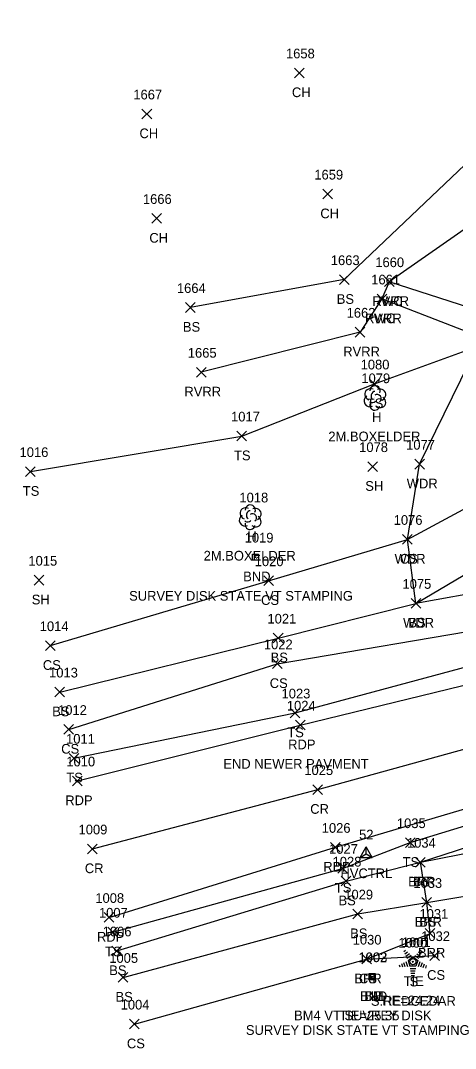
# Model space of a CAD drawing. Extents: x 1443064 to 1445163, y 544063 to 544655.
# Drawn here: x 1443063.6 to 1443153.5, y 544062.5 to 544274.6 of the extents above; entities that cross this region are included whole.
import ezdxf

# ---------------------------------------------------------------- set-up
doc = ezdxf.new("R2010")
doc.units = 0
for name, color, linetype in [('C_A', 7, 'Continuous'), ('C_C', 7, 'Continuous'), ('C_I', 7, 'Continuous'), ('CBP', 7, 'Continuous'), ('CPBM', 7, 'Continuous'), ('CPSM', 7, 'Continuous'), ('L_A', 7, 'Continuous'), ('L_C', 7, 'Continuous'), ('L_I', 7, 'Continuous'), ('L_TIC', 7, 'Continuous'), ('LABL', 7, 'Continuous'), ('LAWA', 7, 'Continuous'), ('LAWE', 7, 'Continuous'), ('LELB', 7, 'Continuous'), ('LTC', 7, 'Continuous'), ('LTD', 7, 'Continuous'), ('M_A', 7, 'Continuous'), ('M_C', 7, 'Continuous'), ('M_I', 7, 'Continuous'), ('MHBP', 7, 'Continuous'), ('P_A', 7, 'Continuous'), ('P_C', 7, 'Continuous'), ('P_I', 7, 'Continuous'), ('P_TIC', 7, 'Continuous'), ('PET', 7, 'Continuous'), ('PRC', 7, 'Continuous')]:
    doc.layers.add(name, color=color, linetype=linetype)

msp = doc.modelspace()

# ---------------------------------------------------------------- linework, layer by layer
at = {"layer": 'CBP'}
for centre, radius in [((1443144.67, 544080.41), 0.625), ((1443144.67, 544080.41), 0.0833), ((1443136.24, 544077.31), 0.625), ((1443136.24, 544077.31), 0.0833)]:
    msp.add_circle(centre, radius, dxfattribs=at)
at = {"layer": 'CPBM'}
for p, q in [((1443135.8, 544076.82), (1443135.8, 544077.82)), ((1443135.8, 544077.82), (1443136.8, 544077.82)), ((1443136.8, 544076.82), (1443135.8, 544076.82)), ((1443136.3, 544077.32), (1443136.3, 544077.32)), ((1443136.3, 544077.32), (1443136.3, 544077.32)), ((1443136.8, 544077.82), (1443136.8, 544076.82))]:
    msp.add_line(p, q, dxfattribs=at)
at = {"layer": 'CPSM'}
for p, q in [((1443133.76, 544101.93), (1443135.01, 544104.09)), ((1443136.26, 544101.93), (1443135.01, 544104.09)), ((1443135.02, 544102.65), (1443135.01, 544104.09)), ((1443133.76, 544101.93), (1443135.02, 544102.65)), ((1443133.76, 544101.93), (1443136.26, 544101.93)), ((1443135.02, 544102.65), (1443135.02, 544102.65)), ((1443135.02, 544102.65), (1443136.26, 544101.93))]:
    msp.add_line(p, q, dxfattribs=at)
at = {"layer": 'L_TIC'}
for points in [[(1443120.19, 544262.82), (1443122.19, 544264.82)], [(1443122.19, 544262.82), (1443120.19, 544264.82)], [(1443088.72, 544254.35), (1443090.72, 544256.35)], [(1443090.72, 544254.35), (1443088.72, 544256.35)], [(1443126.06, 544237.82), (1443128.06, 544239.82)], [(1443128.06, 544237.82), (1443126.06, 544239.82)], [(1443090.76, 544232.79), (1443092.76, 544234.79)], [(1443092.76, 544232.79), (1443090.76, 544234.79)], [(1443129.5, 544220.16), (1443131.5, 544222.16)], [(1443131.5, 544220.16), (1443129.5, 544222.16)], [(1443138.78, 544219.74), (1443140.78, 544221.74)], [(1443140.78, 544219.74), (1443138.78, 544221.74)], [(1443138.78, 544219.74), (1443140.78, 544221.74)], [(1443140.78, 544219.74), (1443138.78, 544221.74)], [(1443097.72, 544214.41), (1443099.72, 544216.41)], [(1443099.72, 544214.41), (1443097.72, 544216.41)], [(1443137.28, 544216.17), (1443139.28, 544218.17)], [(1443139.28, 544216.17), (1443137.28, 544218.17)], [(1443137.28, 544216.17), (1443139.28, 544218.17)], [(1443139.28, 544216.17), (1443137.28, 544218.17)], [(1443132.77, 544209.32), (1443134.77, 544211.32)], [(1443134.77, 544209.32), (1443132.77, 544211.32)], [(1443099.97, 544201.05), (1443101.97, 544203.05)], [(1443101.97, 544201.05), (1443099.97, 544203.05)], [(1443135.73, 544198.63), (1443137.73, 544200.63)], [(1443137.73, 544198.63), (1443135.73, 544200.63)], [(1443108.31, 544187.89), (1443110.31, 544189.89)], [(1443110.31, 544187.89), (1443108.31, 544189.89)], [(1443064.69, 544180.55), (1443066.69, 544182.55)], [(1443066.69, 544180.55), (1443064.69, 544182.55)], [(1443135.34, 544181.58), (1443137.34, 544183.58)], [(1443137.34, 544181.58), (1443135.34, 544183.58)], [(1443145.04, 544182.08), (1443147.04, 544184.08)], [(1443147.04, 544182.08), (1443145.04, 544184.08)], [(1443142.53, 544166.56), (1443144.53, 544168.56)], [(1443144.53, 544166.56), (1443142.53, 544168.56)], [(1443142.53, 544166.56), (1443144.53, 544168.56)], [(1443144.53, 544166.56), (1443142.53, 544168.56)], [(1443066.46, 544158.14), (1443068.46, 544160.14)], [(1443068.46, 544158.14), (1443066.46, 544160.14)], [(1443113.86, 544158.03), (1443115.86, 544160.03)], [(1443115.86, 544158.03), (1443113.86, 544160.03)], [(1443144.28, 544153.36), (1443146.28, 544155.36)], [(1443146.28, 544153.36), (1443144.28, 544155.36)], [(1443144.28, 544153.36), (1443146.28, 544155.36)], [(1443146.28, 544153.36), (1443144.28, 544155.36)], [(1443068.8, 544144.63), (1443070.8, 544146.63)], [(1443070.8, 544144.63), (1443068.8, 544146.63)], [(1443115.84, 544146.19), (1443117.84, 544148.19)], [(1443117.84, 544146.19), (1443115.84, 544148.19)], [(1443115.66, 544140.89), (1443117.66, 544142.89)], [(1443117.66, 544140.89), (1443115.66, 544142.89)], [(1443070.73, 544135.06), (1443072.73, 544137.06)], [(1443072.73, 544135.06), (1443070.73, 544137.06)], [(1443119.32, 544130.74), (1443121.32, 544132.74)], [(1443121.32, 544130.74), (1443119.32, 544132.74)], [(1443072.59, 544127.34), (1443074.59, 544129.34)], [(1443074.59, 544127.34), (1443072.59, 544129.34)], [(1443073.67, 544121.4), (1443075.67, 544123.4)], [(1443075.67, 544121.4), (1443073.67, 544123.4)], [(1443143.13, 544103.98), (1443145.13, 544105.98)], [(1443145.13, 544103.98), (1443143.13, 544105.98)], [(1443145.21, 544099.93), (1443147.21, 544101.93)], [(1443147.21, 544099.93), (1443145.21, 544101.93)], [(1443145.21, 544099.93), (1443147.21, 544101.93)], [(1443147.21, 544099.93), (1443145.21, 544101.93)], [(1443129.13, 544098.67), (1443131.13, 544100.67)], [(1443131.13, 544098.67), (1443129.13, 544100.67)], [(1443129.86, 544096.05), (1443131.86, 544098.05)], [(1443131.86, 544096.05), (1443129.86, 544098.05)], [(1443146.52, 544091.64), (1443148.52, 544093.64)], [(1443148.52, 544091.64), (1443146.52, 544093.64)], [(1443146.52, 544091.64), (1443148.52, 544093.64)], [(1443148.52, 544091.64), (1443146.52, 544093.64)], [(1443132.27, 544089.26), (1443134.27, 544091.26)], [(1443134.27, 544089.26), (1443132.27, 544091.26)], [(1443081.68, 544085.51), (1443083.68, 544087.51)], [(1443083.68, 544085.51), (1443081.68, 544087.51)], [(1443147.23, 544085.26), (1443149.23, 544087.26)], [(1443149.23, 544085.26), (1443147.23, 544087.26)], [(1443082.51, 544081.64), (1443084.51, 544083.64)], [(1443084.51, 544081.64), (1443082.51, 544083.64)], [(1443148.15, 544080.67), (1443150.15, 544082.67)], [(1443150.15, 544080.67), (1443148.15, 544082.67)], [(1443134.09, 544079.94), (1443136.09, 544081.94)], [(1443136.09, 544079.94), (1443134.09, 544081.94)], [(1443134.09, 544079.94), (1443136.09, 544081.94)], [(1443136.09, 544079.94), (1443134.09, 544081.94)], [(1443083.81, 544076.17), (1443085.81, 544078.17)], [(1443085.81, 544076.17), (1443083.81, 544078.17)], [(1443086.16, 544066.54), (1443088.16, 544068.54)], [(1443088.16, 544066.54), (1443086.16, 544068.54)]]:
    msp.add_lwpolyline(points, dxfattribs=at)
at = {"layer": 'LABL'}
msp.add_lwpolyline([(1443135.09, 544080.94), (1443148.23, 544086.26), (1443147.52, 544092.64), (1443146.21, 544100.93), (1443174.96, 544106.59), (1443195.01, 544110.55), (1443196.95, 544107.58), (1443201, 544099.13), (1443204.98, 544089.82), (1443210.37, 544081.53)], dxfattribs=at)
at = {"layer": 'LAWA'}
msp.add_lwpolyline([(1443161.29, 544157.23), (1443145.28, 544154.36), (1443143.53, 544167.56), (1443146.04, 544183.08), (1443157.94, 544207.35), (1443163.64, 544207.35), (1443166.87, 544211.98), (1443169.79, 544215.76), (1443171.76, 544225.15), (1443198.4, 544243.33), (1443223.22, 544247.5), (1443248.61, 544240.73), (1443289.53, 544254.52), (1443328.33, 544272.01), (1443354.38, 544286)], dxfattribs=at)
at = {"layer": 'LAWE'}
for points in [[(1443627.73, 544516.96), (1443602.93, 544465.06), (1443560.09, 544445.87), (1443514.11, 544419.1), (1443476.33, 544389.4), (1443439.4, 544357.75), (1443402.97, 544339.11), (1443368.14, 544318.06), (1443323.16, 544292.42), (1443281.44, 544273.46), (1443240.37, 544261.14), (1443193.33, 544260.65), (1443164.34, 544237.83), (1443139.78, 544220.74), (1443138.28, 544217.17), (1443133.77, 544210.32), (1443100.97, 544202.05)], [(1443196.33, 544167.63), (1443194.95, 544177.18), (1443185.57, 544192.33), (1443177.49, 544199.81), (1443166.87, 544211.98), (1443139.78, 544220.74)], [(1443194.34, 544166.63), (1443188.72, 544173.88), (1443182.02, 544189.58), (1443171.16, 544195.16), (1443163.64, 544207.35), (1443138.28, 544217.17)]]:
    msp.add_lwpolyline(points, dxfattribs=at)
at = {"layer": 'LELB'}
for points in [[(1443623.25, 544521.72), (1443599.67, 544467.52), (1443557.8, 544451.16), (1443512.32, 544424.47), (1443473.97, 544391.39), (1443436.99, 544360.77), (1443402.58, 544340.48), (1443365.21, 544324.82), (1443319.81, 544300.23), (1443279.76, 544280.29), (1443239.01, 544265.94), (1443191.15, 544266.77), (1443161, 544250.15), (1443130.5, 544221.16), (1443098.72, 544215.41)], [(1443073.59, 544128.34), (1443116.66, 544141.89), (1443162.8, 544149.75), (1443198.07, 544157.24), (1443242.5, 544173.41), (1443262.84, 544182.05), (1443307.11, 544199.46), (1443348.85, 544214.35), (1443394.74, 544233.02), (1443435.02, 544243.93), (1443473.16, 544259.47), (1443514.32, 544272.16), (1443555.56, 544285.54), (1443605.06, 544302.52), (1443644.56, 544313.72), (1443676.09, 544324.26), (1443689.45, 544326.75), (1443708.55, 544330.01), (1443714.07, 544333.45), (1443742.84, 544349.83), (1443793.92, 544368.99), (1443822.61, 544377.56)], [(1443074.67, 544122.4), (1443120.32, 544131.74), (1443165.11, 544143.77), (1443199.58, 544153.13), (1443245.24, 544167.88), (1443264.59, 544177.57), (1443308.86, 544194.48), (1443350.56, 544209.36), (1443397.32, 544225.82), (1443437.1, 544238.98), (1443476.53, 544253.14), (1443516.75, 544265.8), (1443558.95, 544280.95), (1443607.52, 544296.39), (1443646.45, 544306.32), (1443685.12, 544319.06), (1443714.26, 544329.16), (1443721.31, 544331.26), (1443744.28, 544345.57), (1443795.65, 544366.53), (1443822.61, 544377.56)], [(1443082.68, 544086.51), (1443130.13, 544099.67), (1443144.13, 544104.98), (1443172.72, 544113.76), (1443212.83, 544125.42), (1443253.97, 544138.87), (1443319.39, 544160.76), (1443361, 544176.06), (1443409.52, 544193.8), (1443447.54, 544206.03), (1443485.93, 544218.99), (1443527.17, 544233.73), (1443570.65, 544246.93), (1443621.44, 544264.66), (1443656.15, 544276.08), (1443695.78, 544288.38), (1443720.36, 544296.79), (1443749.28, 544306.83), (1443759.63, 544310.57), (1443806.78, 544328.14), (1443835.8, 544338.24)], [(1443065.69, 544181.55), (1443109.31, 544188.89), (1443136.73, 544199.63), (1443157.94, 544207.35), (1443161.61, 544194.55), (1443179.72, 544186.99), (1443184.46, 544169.42), (1443186.09, 544163.69), (1443190.43, 544160.91), (1443201.88, 544165.55), (1443201.36, 544168), (1443198.62, 544178.69), (1443186.97, 544194.77), (1443179.33, 544201.28), (1443169.79, 544215.76), (1443186.02, 544215.66), (1443204.39, 544216.66), (1443224.03, 544235.31), (1443250.92, 544228.56), (1443292.51, 544245.42), (1443354.38, 544286)], [(1443069.8, 544145.63), (1443114.86, 544159.03), (1443143.53, 544167.56), (1443179.72, 544186.99)], [(1443071.73, 544136.06), (1443116.84, 544147.19), (1443145.28, 544154.36), (1443163.29, 544164.96), (1443184.46, 544169.42)], [(1443083.51, 544082.64), (1443130.86, 544097.05), (1443146.21, 544100.93), (1443173.82, 544109.88), (1443194, 544113.59), (1443213.82, 544112.65), (1443216.18, 544114.05), (1443217.58, 544114.04), (1443220.05, 544115), (1443228.99, 544115.61), (1443239.88, 544119.45), (1443281.32, 544122.33)], [(1443084.81, 544077.17), (1443133.27, 544090.26), (1443147.52, 544092.64), (1443177.12, 544097.61), (1443201, 544099.13)], [(1443087.16, 544067.54), (1443135.09, 544080.94), (1443149.15, 544081.67)]]:
    msp.add_lwpolyline(points, dxfattribs=at)
at = {"layer": 'LTC'}
for p, q in [((1443142.8, 544082.51), (1443143.16, 544082.77)), ((1443146.2, 544082.76), (1443146.62, 544082.45)), ((1443143.01, 544082.05), (1443143.54, 544082.43)), ((1443143.22, 544081.58), (1443143.93, 544082.09)), ((1443143.43, 544081.12), (1443144.31, 544081.76)), ((1443143.66, 544080.66), (1443144.67, 544081.4)), ((1443143.66, 544080.66), (1443144.04, 544079.47)), ((1443144.67, 544081.4), (1443145.66, 544080.67)), ((1443145.09, 544081.71), (1443145.9, 544081.12)), ((1443145.66, 544080.67), (1443145.27, 544079.47)), ((1443145.46, 544082.06), (1443146.14, 544081.56)), ((1443145.83, 544082.41), (1443146.38, 544082.01)), ((1443141.84, 544079.79), (1443141.99, 544079.33)), ((1443142.29, 544080.01), (1443142.5, 544079.36)), ((1443142.75, 544080.23), (1443143.02, 544079.39)), ((1443143.2, 544080.44), (1443143.53, 544079.42)), ((1443145.27, 544079.47), (1443144.04, 544079.47)), ((1443145.24, 544078.97), (1443144.09, 544078.97)), ((1443145.15, 544078.47), (1443144.16, 544078.47)), ((1443146.1, 544080.4), (1443145.76, 544079.36)), ((1443146.55, 544080.15), (1443146.26, 544079.27)), ((1443146.99, 544079.9), (1443146.75, 544079.17)), ((1443147.44, 544079.65), (1443147.25, 544079.08)), ((1443145.07, 544077.97), (1443144.24, 544077.97)), ((1443144.98, 544077.47), (1443144.31, 544077.47))]:
    msp.add_line(p, q, dxfattribs=at)
at = {"layer": 'LTD'}
for p, q in [((1443136.8, 544196.8), (1443136.8, 544196.8)), ((1443136.8, 544196.8), (1443136.8, 544196.8)), ((1443111.05, 544172.19), (1443111.05, 544172.19)), ((1443111.05, 544172.19), (1443111.05, 544172.19))]:
    msp.add_line(p, q, dxfattribs=at)
for centre in [(1443136.85, 544198.23), (1443111.09, 544173.62)]:
    msp.add_arc(centre, 1.05, 335.5272, 180.9563, dxfattribs=at)
for centre, major_axis, ratio, start_param, end_param in [((1443135.72, 544196.09), (0.58, -1.04), 0.959034, 3.141593, 6.283185), ((1443136.01, 544197.46), (1.21, -0.51), 0.895232, 1.570796, 4.712389), ((1443136.59, 544197.26), (-0.208, -0.792), 0.645439, 3.141593, 6.283185), ((1443137.3, 544196.63), (-0.5, 0.667), 0.989748, 3.141593, 6.283185), ((1443137.84, 544197.38), (-1.14, -0.48), 0.949671, 1.570796, 4.712389), ((1443136.8, 544195.3), (0.26, 1.06), 0.942809, 1.570796, 4.712389), ((1443136.34, 544196.05), (-0.625, -0.083), 0.423636, 0, 3.141593), ((1443137.8, 544195.96), (-1.09, 0.79), 0.841452, 1.570796, 4.712389), ((1443110.26, 544172.86), (1.21, -0.51), 0.895232, 1.570796, 4.712389), ((1443112.09, 544172.77), (-1.14, -0.48), 0.949671, 1.570796, 4.712389), ((1443109.96, 544171.48), (0.58, -1.04), 0.959034, 3.141593, 6.283185), ((1443110.84, 544172.65), (-0.208, -0.792), 0.645439, 3.141593, 6.283185), ((1443111.55, 544172.02), (-0.5, 0.667), 0.989748, 3.141593, 6.283185), ((1443112.05, 544171.36), (-1.09, 0.79), 0.841452, 1.570796, 4.712389), ((1443111.05, 544170.69), (0.26, 1.06), 0.942809, 1.570796, 4.712389), ((1443110.59, 544171.44), (-0.625, -0.083), 0.423636, 0, 3.141593)]:
    msp.add_ellipse(centre, major_axis=major_axis, ratio=ratio, start_param=start_param, end_param=end_param, dxfattribs=at)
at = {"layer": 'MHBP'}
for points in [[(1443111.51, 544164.54), (1443112.76, 544164.54), (1443112.76, 544163.29), (1443111.51, 544163.29)], [(1443135.61, 544077.94), (1443136.86, 544077.94), (1443136.86, 544076.69), (1443135.61, 544076.69)]]:
    msp.add_lwpolyline(points, close=True, dxfattribs=at)
for centre in [(1443112.13, 544163.91), (1443136.24, 544077.31)]:
    msp.add_circle(centre, 0.0833, dxfattribs=at)
at = {"layer": 'P_TIC'}
for points in [[(1443120.41, 544128.24), (1443122.41, 544130.24)], [(1443122.41, 544128.24), (1443120.41, 544130.24)], [(1443074.39, 544116.71), (1443076.39, 544118.71)], [(1443076.39, 544116.71), (1443074.39, 544118.71)], [(1443124.02, 544114.93), (1443126.02, 544116.93)], [(1443126.02, 544114.93), (1443124.02, 544116.93)], [(1443077.47, 544102.68), (1443079.47, 544104.68)], [(1443079.47, 544102.68), (1443077.47, 544104.68)], [(1443127.67, 544103.01), (1443129.67, 544105.01)], [(1443129.67, 544103.01), (1443127.67, 544105.01)], [(1443080.93, 544088.54), (1443082.93, 544090.54)], [(1443082.93, 544088.54), (1443080.93, 544090.54)]]:
    msp.add_lwpolyline(points, dxfattribs=at)
at = {"layer": 'PET'}
for points in [[(1443075.39, 544117.71), (1443121.41, 544129.24), (1443165.99, 544140.07), (1443200.71, 544149.88), (1443246.42, 544165.39), (1443265.96, 544172.48), (1443311.2, 544187.88), (1443352.92, 544202.76), (1443399.28, 544220.13), (1443438.78, 544233.67), (1443478.75, 544247.35), (1443518.41, 544260.6), (1443561.23, 544274.05), (1443611.7, 544290.5), (1443646.84, 544301.68), (1443684.98, 544314.55), (1443724.57, 544327.54), (1443735.41, 544331.22), (1443748.81, 544336.36), (1443799.43, 544353.96), (1443827.31, 544364.14)], [(1443081.93, 544089.54), (1443128.67, 544104.01), (1443173.03, 544117.15), (1443209.23, 544128.71), (1443253.49, 544142.88), (1443273.3, 544149.07), (1443318.27, 544165.2), (1443359.78, 544179.84), (1443408.54, 544196.96), (1443445.92, 544210.12), (1443484.92, 544223.61), (1443525.67, 544237.02), (1443568.63, 544251.04), (1443620.57, 544267.93), (1443654.52, 544278.93), (1443694.69, 544292.43), (1443717.24, 544299.44), (1443752.8, 544310.97), (1443757.72, 544314.31), (1443805.74, 544330.07), (1443835.35, 544341.18)]]:
    msp.add_lwpolyline(points, dxfattribs=at)
at = {"layer": 'PRC'}
msp.add_lwpolyline([(1443078.47, 544103.68), (1443125.02, 544115.93), (1443169.41, 544128.22), (1443204.47, 544139.4), (1443250.36, 544154.3), (1443269.99, 544160.83), (1443315.13, 544176.71), (1443356.58, 544191.19), (1443403.59, 544208.05), (1443442.67, 544222.02), (1443482.15, 544235.41), (1443522.16, 544248.37), (1443565.47, 544262.64), (1443616.51, 544279.34), (1443650.9, 544289.93), (1443689.58, 544302.53), (1443728.44, 544315.77), (1443753.53, 544324.68), (1443803.56, 544342.2), (1443830.96, 544352.16)], dxfattribs=at)

# ---------------------------------------------------------------- texts
at = {"layer": 'C_A'}
for s, p in [('HVCTRL', (1443129.71, 544097.65)), ('TIE', (1443142.75, 544075.41)), ('TIE', (1443134.32, 544072.31)), ('BM', (1443134.61, 544072.32))]:
    msp.add_text(s, height=2, dxfattribs=at).set_placement(p)
at = {"layer": 'C_C'}
for s, p in [('TIE=24.24', (1443137.9, 544071.41)), ('BM4 VT SUVREY DISK', (1443120.13, 544068.32))]:
    msp.add_text(s, height=2, dxfattribs=at).set_placement(p)
at = {"layer": 'C_I'}
for s, p in [('52', (1443133.55, 544105.65)), ('1001', (1443142.39, 544083.41)), ('1002', (1443133.39, 544080.31)), ('1003', (1443133.45, 544080.32))]:
    msp.add_text(s, height=2, dxfattribs=at).set_placement(p)
at = {"layer": 'L_A'}
for s, p in [('CH', (1443119.68, 544258.82)), ('CH', (1443088.2, 544250.35)), ('CH', (1443125.55, 544233.82)), ('CH', (1443090.24, 544228.79)), ('BS', (1443128.94, 544216.16)), ('RVRR', (1443136.29, 544215.74)), ('WC', (1443138.08, 544215.74)), ('RVRR', (1443134.79, 544212.17)), ('WC', (1443136.59, 544212.17)), ('BS', (1443097.16, 544210.41)), ('RVRR', (1443130.28, 544205.32)), ('RVRR', (1443097.48, 544197.05)), ('TS', (1443135.14, 544194.63)), ('H', (1443136.24, 544191.8)), ('TS', (1443107.72, 544183.89)), ('TS', (1443064.1, 544176.55)), ('SH', (1443134.83, 544177.58)), ('WDR', (1443143.4, 544178.08)), ('H', (1443110.48, 544167.19)), ('WDR', (1443140.89, 544162.56)), ('CS', (1443141.97, 544162.56)), ('SH', (1443065.95, 544154.14)), ('CS', (1443113.3, 544154.03)), ('WDR', (1443142.64, 544149.36)), ('BS', (1443143.72, 544149.36)), ('BS', (1443115.28, 544142.19)), ('CS', (1443068.24, 544140.63)), ('CS', (1443115.1, 544136.89)), ('BS', (1443070.17, 544131.06)), ('TS', (1443118.73, 544126.74)), ('CS', (1443072.03, 544123.34)), ('TS', (1443073.08, 544117.4)), ('TS', (1443142.54, 544099.98)), ('BRR', (1443143.7, 544095.93)), ('BS', (1443144.65, 544095.93)), ('TS', (1443128.54, 544094.67)), ('BS', (1443129.3, 544092.05)), ('BRR', (1443145.01, 544087.64)), ('BS', (1443145.96, 544087.64)), ('BS', (1443131.71, 544085.26)), ('TS', (1443081.09, 544081.51)), ('BRR', (1443145.71, 544081.26)), ('BS', (1443081.95, 544077.64)), ('CS', (1443147.6, 544076.67)), ('BRR', (1443132.58, 544075.94)), ('CS', (1443133.53, 544075.94)), ('S', (1443143.99, 544075.31)), ('BS', (1443083.25, 544072.17)), ('CS', (1443085.6, 544062.54))]:
    msp.add_text(s, height=2, dxfattribs=at).set_placement(p)
at = {"layer": 'L_C'}
for s, p in [('2M.BOXELDER', (1443127.2, 544187.8)), ('2M.BOXELDER', (1443101.45, 544163.19)), ('S.REDCEDAR', (1443136, 544071.31))]:
    msp.add_text(s, height=2, dxfattribs=at).set_placement(p)
at = {"layer": 'L_I'}
for s, p in [('1658', (1443118.45, 544266.82)), ('1667', (1443086.93, 544258.35)), ('1659', (1443124.31, 544241.82)), ('1666', (1443088.91, 544236.79)), ('1663', (1443127.71, 544224.16)), ('1660', (1443136.9, 544223.74)), ('1660', (1443136.9, 544223.74)), ('1661', (1443136.06, 544220.17)), ('1661', (1443136.06, 544220.17)), ('1664', (1443095.93, 544218.41)), ('1662', (1443130.98, 544213.32)), ('1665', (1443098.18, 544205.05)), ('1080', (1443133.87, 544202.63)), ('1079', (1443134.02, 544199.8)), ('1017', (1443107.11, 544191.89)), ('1016', (1443063.43, 544184.55)), ('1078', (1443133.57, 544185.58)), ('1077', (1443143.27, 544186.08)), ('1018', (1443108.84, 544175.19)), ('1076', (1443140.7, 544170.56)), ('1076', (1443140.7, 544170.56)), ('1015', (1443065.26, 544162.14)), ('1020', (1443112, 544162.03)), ('1075', (1443142.51, 544157.36)), ('1075', (1443142.51, 544157.36)), ('1014', (1443067.6, 544148.63)), ('1021', (1443114.63, 544150.19)), ('1022', (1443113.89, 544144.89)), ('1013', (1443069.53, 544139.06)), ('1023', (1443117.54, 544134.74)), ('1012', (1443071.38, 544131.34)), ('1011', (1443073.04, 544125.4)), ('1035', (1443141.36, 544107.98)), ('1034', (1443143.44, 544103.93)), ('1034', (1443143.44, 544103.93)), ('1027', (1443127.35, 544102.67)), ('1028', (1443128.08, 544100.05)), ('1033', (1443144.75, 544095.64)), ('1033', (1443144.75, 544095.64)), ('1029', (1443130.49, 544093.26)), ('1007', (1443079.83, 544089.51)), ('1031', (1443146.02, 544089.26)), ('1006', (1443080.6, 544085.64)), ('1030', (1443132.23, 544083.94)), ('1030', (1443132.23, 544083.94)), ('1000', (1443141.67, 544083.31)), ('1032', (1443146.38, 544084.67)), ('1005', (1443081.96, 544080.17)), ('1004', (1443084.31, 544070.54))]:
    msp.add_text(s, height=2, dxfattribs=at).set_placement(p)
at = {"layer": 'LTC'}
msp.add_text('.', height=1.04, rotation=270, dxfattribs=at).set_placement((1443144.55, 544080.41))
at = {"layer": 'M_A'}
for p in [(1443109.62, 544158.91), (1443133.73, 544072.31)]:
    msp.add_text('BND', height=2, dxfattribs=at).set_placement(p)
at = {"layer": 'M_C'}
for s, p in [('SURVEY DISK STATE VT STAMPING', (1443086.06, 544154.91)), ('TIE=25.35', (1443129.47, 544068.31)), ('SURVEY DISK STATE VT STAMPING', (1443110.17, 544065.31))]:
    msp.add_text(s, height=2, dxfattribs=at).set_placement(p)
at = {"layer": 'M_I'}
for s, p in [('1019', (1443109.92, 544166.91)), ('1002', (1443133.39, 544080.31))]:
    msp.add_text(s, height=2, dxfattribs=at).set_placement(p)
at = {"layer": 'P_A'}
for s, p in [('RDP', (1443118.9, 544124.24)), ('RDP', (1443072.87, 544112.71)), ('CR', (1443123.46, 544110.93)), ('CR', (1443076.91, 544098.68)), ('RDP', (1443126.16, 544099.01)), ('RDP', (1443079.42, 544084.54))]:
    msp.add_text(s, height=2, dxfattribs=at).set_placement(p)
at = {"layer": 'P_C'}
msp.add_text('END NEWER PAVMENT', height=2, dxfattribs=at).set_placement((1443105.52, 544120.24))
at = {"layer": 'P_I'}
for s, p in [('1024', (1443118.64, 544132.24)), ('1010', (1443073.09, 544120.71)), ('1025', (1443122.25, 544118.93)), ('1009', (1443075.62, 544106.68)), ('1026', (1443125.84, 544107.01)), ('1008', (1443079.08, 544092.54))]:
    msp.add_text(s, height=2, dxfattribs=at).set_placement(p)

doc.saveas('drawing.dxf')
